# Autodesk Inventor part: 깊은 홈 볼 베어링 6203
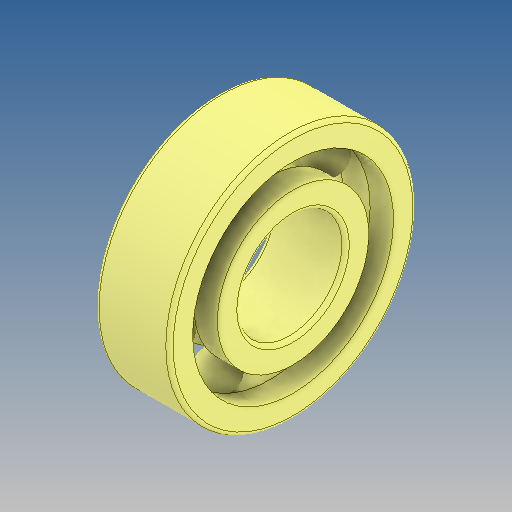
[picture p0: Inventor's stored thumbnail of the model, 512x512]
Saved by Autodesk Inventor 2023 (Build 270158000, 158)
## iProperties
Created: 2025-03
Part Number: 깊은 홈 볼 베어링 6203
Material: 강철, 연강
Description: 깊은 그루브 볼 베어링
Document SubType Name: Modeling
Designer: Admin
Density: 7.85 g/cm^3
Appearance: 기본값
Author: jhkim
Sending System: Autodesk Inventor 2025
Preprocessor: ST-DEVELOPER v20
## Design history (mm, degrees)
node "깊은 홈 볼 베어링 62031"
node "솔리드1"
node "솔리드2"
node "솔리드3"
node "솔리드4"
node "솔리드5"
node "솔리드6"
node "솔리드7"
node "솔리드8"
node "솔리드9"
body "Solid1"
node "Solid1:1"
node "Solid1:2"
node "Solid1:3"
node "Solid1:4"
node "Solid1:5"
node "Solid1:6"
node "Solid1:7"
node "Solid1:8"
